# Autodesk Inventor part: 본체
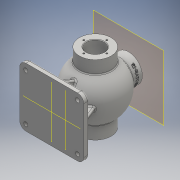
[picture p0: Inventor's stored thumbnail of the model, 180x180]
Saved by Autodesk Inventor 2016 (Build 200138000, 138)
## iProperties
Created: 2017-01
Part Number: 본체
Material: 일반
Document SubType Name: Modeling
Designer: Administrator
Density: 1 g/cm^3
Appearance: 기본값
Author: Administrator
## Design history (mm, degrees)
sketch "스케치1"
  geometry: L1 (0, 0)-(125, 0); L2 (125, 0)-(125, -115); L3 (125, -115)-(0, -115); L4 (0, -115)-(0, 0)
  constraints: 8 end point, 2 parallel, 1 horizontal, 1 perpendicular
  dimensions: "d0" = 115 distance of L1.end L2.end; "d1" = 125 distance of L2.end L3.end
extrude "돌출1" new body sketch "스케치1" distance "d2" = 10; taper "d3" = 0 deg
sketch "스케치2"
  geometry: L1 (-125, 0)-(-125, 115) reference; L2 (-125, 0)-(0, 0) reference; 1 further point
  dimensions: "d4" = 12 distance from line of L1 point (-113, 12); "d5" = 12 distance from line of L2 point (-113, 12)
hole "구멍1" sketch "스케치2" at (-113, 12) diameter "d6" = 8; stored, may be unused: countersink angle "d10" = 90 deg, drill point angle "d12" = 118 deg; dims "d7" = 6, "d8" = 12, "d9" = 3, "d11" = 8
fillet "모깎기1" dims "d19" = 12
node "작업 평면1"
sketch "스케치3"
  geometry: L1 (113.5, 116)-(113.5, 102.5); L2 (113.5, 85)-(-22.5, 85); L3 (-22.5, 102.5)-(-22.5, 116); L4 (91, 0)-(0, 0) reference; L5 (-12, 10)-(-12, 0) reference; L6 (-22.5, 116)-(2.512, 116); L7 (88.488, 116)-(113.5, 116); L8 (-6.5, 102.5)-(6.222, 102.5); L9 (-6.5, 102.5)-(-22.5, 102.5); L10 (113.5, 102.5)-(97.5, 102.5); L11 (97.5, 102.5)-(97.5, 103.5); L12 (97.5, 103.5)-(95.75, 103.5); L13 (95.75, 103.5)-(95.75, 102.5); L14 (95.75, 102.5)-(84.778, 102.5); A1 r 53 centre (45.5, 85) between (88.488, 116) and (2.512, 116); A2 r 43 centre (45.5, 85) between (84.778, 102.5) and (6.222, 102.5); 2 further points
  constraints: 24 end point, 7 perpendicular, 4 point on circle, 3 parallel, 2 centre point, 2 horizontal, 2 point on line, 1 midpoint, 1 vertical
  dimensions: "d22" = 136 distance of L3.end L1.start; "d23" = 85 distance between parallel lines of L4 L2; "d24" = 31 distance of L2.end L3.end; "d25" = 10.5 distance between parallel lines of L5 L3; "d26" = 53 radius of A1; "d28" = 43 radius of A2; "d36" = 17.5 distance between parallel lines of L2 L8; "d39" = 16 distance of L1.end L10.end; "d40" = 18.5 distance between parallel lines of L2 L12; "d41" = 17.5 distance between parallel lines of L2 L14; "d42" = 17.5 distance between parallel lines of L2 L10; "d43" = 1.75 distance of L11.end L12.end; "d44" = 136 distance between parallel lines of L3 L1; "d45" = 31 distance between parallel lines of L2 L6; "d46" = 68 distance of L2.end A1.centre
revolve "회전1" sketch "스케치3" stored, may be unused: angle "d32" = 90 deg
fillet "모깎기2" dims "d47" = 3
chamfer "모따기1" distance "d48" = 1; stored, may be unused: second distance "d49" = 2, angle "d50" = 45 deg
node "작업 평면2"
sketch "스케치4"
  geometry: L1 (-93.5, -125.5)-(-31.5, -125.5) reference; L2 (-125, -103)-(-125, -12) reference; C1 r 27 at (-62.5, -57.5); 1 further point
  constraints: 1 centre point
  dimensions: "d52" = 68 distance from line of C1.centre L1; "d53" = 62.5 distance from line of L2 C1.centre; "d54" = 54 diameter of C1
extrude "돌출2" join sketch "스케치4" stored distance "d55" = 10; taper "d56" = 0 deg
sketch "스케치5"
  geometry: C1 r 13 at (0, 0); 1 further point
  constraints: 1 centre point
  dimensions: "d57" = 26 diameter of C1
extrude "돌출3" cut sketch "스케치5" distance "d58" = 58; taper "d59" = 0 deg
fillet "모깎기3" dims "d60" = 3
chamfer "모따기2" distance "d61" = 1; stored, may be unused: second distance "d62" = 2, angle "d63" = 45 deg
sketch "스케치6" dims "d64" = 40
  geometry: 3 further points
  constraints: 1 horizontal alignment, 2 other
hole "구멍2" sketch "스케치6" at (-20, 0) diameter "d65" = 3.242; stored, may be unused: countersink angle "d69" = 90 deg, drill point angle "d71" = 118 deg; dims "d66" = 9, "d67" = 12, "d68" = 3, "d70" = 11
sketch "스케치7" dims "d75" = 48
  geometry: 3 further points
  constraints: 1 vertical alignment, 2 other
hole "구멍3" sketch "스케치7" at (0, 24) diameter "d76" = 3.242; stored, may be unused: countersink angle "d80" = 90 deg, drill point angle "d82" = 118 deg; dims "d77" = 16, "d78" = 12, "d79" = 3, "d81" = 19
sketch "스케치8" dims "d86" = 45
  geometry: 3 further points
  constraints: 1 vertical alignment, 2 other
hole "구멍4" sketch "스케치8" at (0, 22.5) diameter "d87" = 3.242; stored, may be unused: countersink angle "d91" = 90 deg, drill point angle "d93" = 118 deg; dims "d88" = 12, "d89" = 12, "d90" = 3, "d92" = 15
node "작업 평면3"
sketch "스케치11"
  geometry: L1 (101, 10)-(110, 10) reference; L2 (103, 10)-(86.485, 50.876); L3 (103, 10)-(-2, 10); L4 (101, 10)-(0, 10) reference; L5 (14.515, 50.876)-(-2, 10); L6 (-9, 10)-(0, 10) reference; L7 (113, 0)-(113, 7) reference; L8 (-12, 7)-(-12, 0) reference; A1 r 49.592 centre (50.5, 85) between (14.515, 50.876) and (86.485, 50.876)
  constraints: 6 end point, 2 point on circle, 2 point on line, 1 centre point
  dimensions: "d114" = 112 deg angle of L1 L2; "d115" = 112 deg angle of L6 L5; "d116" = 10 distance from line of L7 L2.start; "d117" = 10 distance from line of L8 L3.end
extrude "돌출5" join sketch "스케치11" stored distance "d118" = 8; taper "d119" = 0 deg
sketch "스케치12"
  geometry: L1 (79.219, 44.109)-(93, 10); L2 (91, 10)-(100, 10) reference; L3 (103, 7)-(103, 0) reference; A1 r 53 centre (45.5, 85) between (87.613, 117.179) and (87.613, 52.821) reference; 1 further point
  constraints: 2 end point, 1 point on circle
  dimensions: "d120" = 112 deg angle of L2 L1; "d121" = 0 distance from line of L2 L1.end; "d122" = 10 distance from line of L3 L1.end
feature "리브2" sketch "스케치12" dims "d123" = 1, "d124" = 8, "d125" = 0, "d126" = 0, "d127" = 1, "d128" = 1
fillet "모깎기4" dims "d129" = 3
fillet "모깎기5" dims "d130" = 3
node "작업 평면4"
sketch "스케치14"
  geometry: L1 (23.761, 142.475)-(65.239, 142.475); L2 (65.239, 142.475)-(65.239, 137.525); L3 (65.239, 137.525)-(23.761, 137.525); L4 (23.761, 137.525)-(23.761, 142.475); L5 (113.5, 54)-(113.5, 116) reference; L6 (72.5, 150)-(18.5, 150) reference; 3 further points
  constraints: 2 midpoint, 2 other
  dimensions: "d134" = 69 distance from line of L5 point (44.5, 137.525); "d135" = 10 distance from line of L6 point (65.239, 140)
feature "엠보싱2" sketch "스케치14" dims "d0" = 115, "d1" = 125, "d19" = 12, "d136" = 0.5, "d137" = 0
node "솔리드1"
pattern_linear "직사각형 패턴1" dims "d15" = 101, "d18" = 91
pattern_circular "원형 패턴1" dims angle "d73" = 360 deg
pattern_circular "원형 패턴2" dims angle "d84" = 360 deg
pattern_circular "원형 패턴3" dims angle "d95" = 360 deg
mirror "대칭1"
other parameters: "d20" = -62.5, "d21" = 106, "d97" = -57.5, "d133" = 27
